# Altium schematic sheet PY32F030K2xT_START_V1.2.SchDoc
size 304 x 241 mm; SheetNumber: 1; SheetTotal: 1
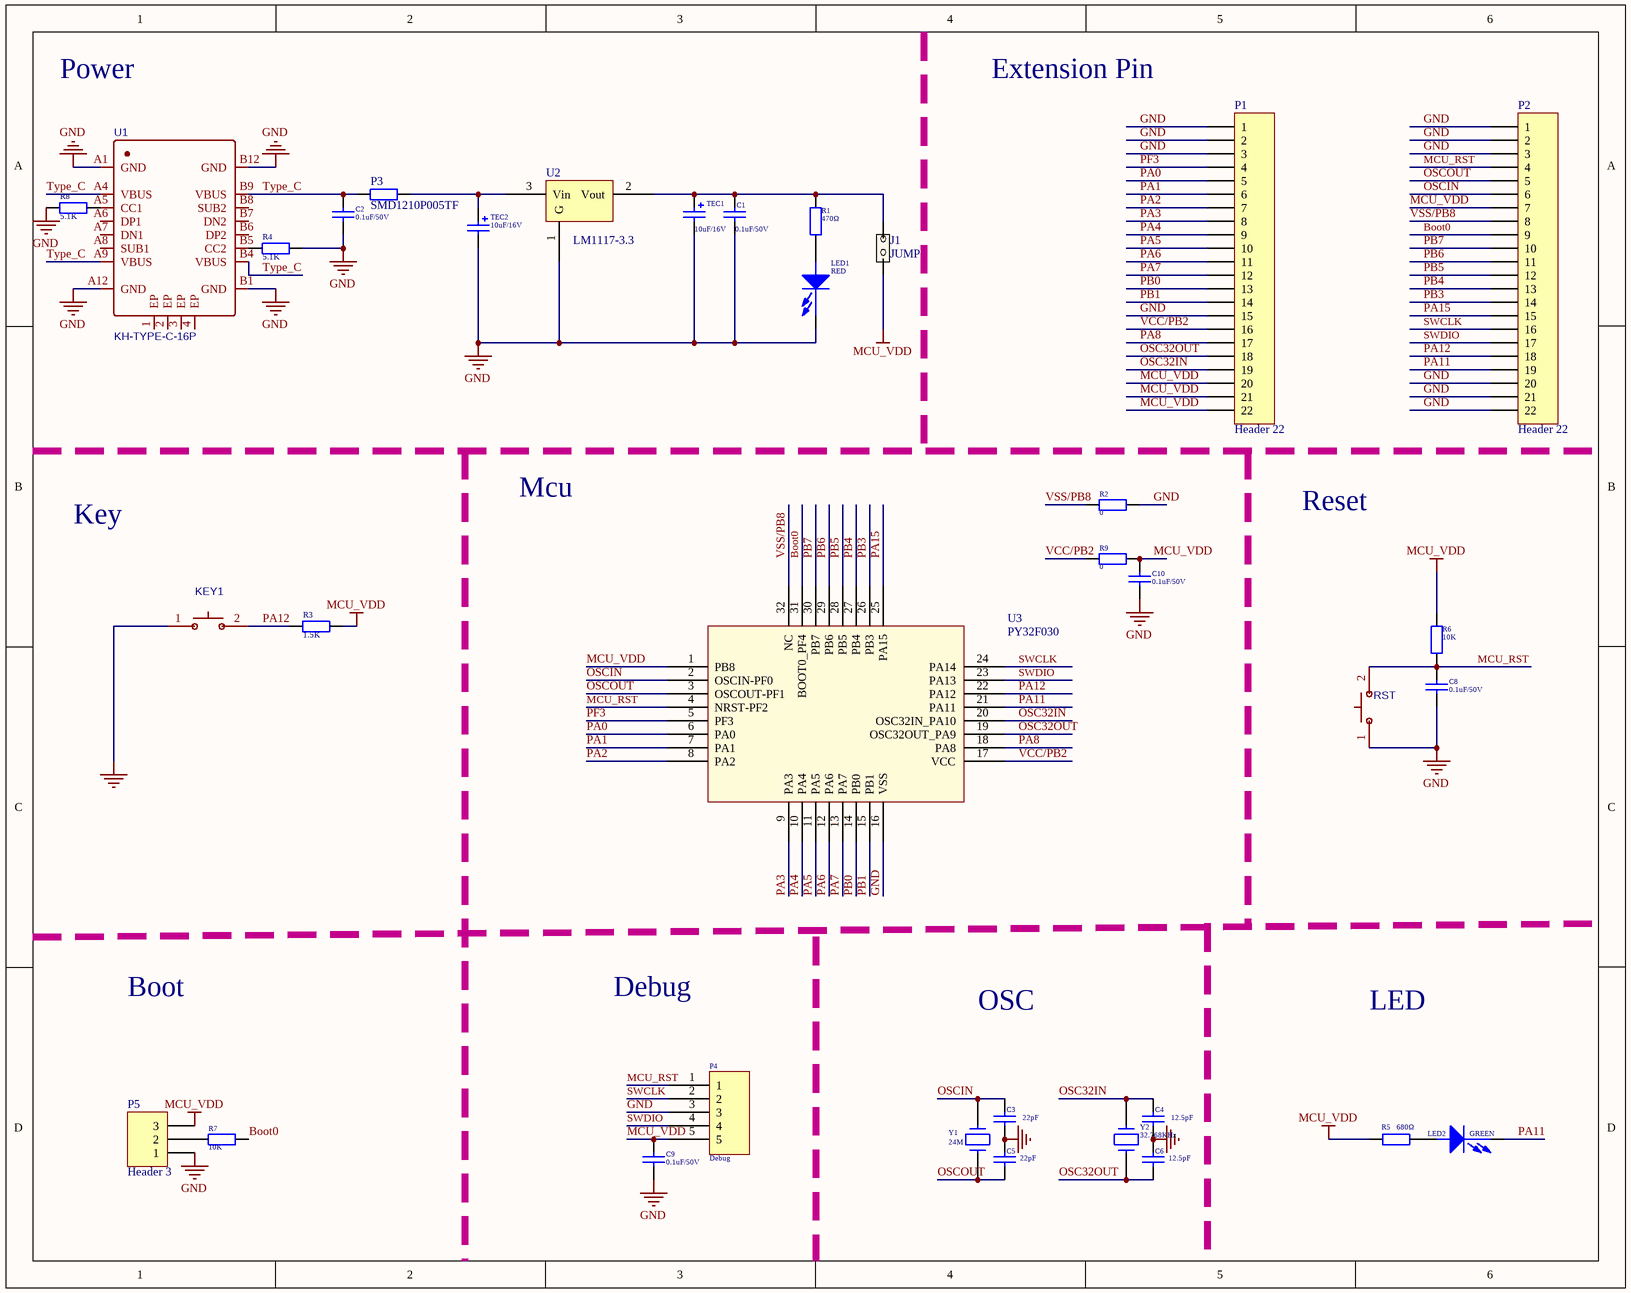
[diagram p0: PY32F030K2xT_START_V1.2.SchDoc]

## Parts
C1  0.1uF/50V  [0603C]
C2  0.1uF/50V  [0603C]
C3  22pF  [0603C]
C4  12.5pF  [0603C]
C5  22pF  [0603C]
C6  12.5pF  [0603C]
C8  0.1uF/50V  [0603C]
C9  0.1uF/50V  [0603C]
C10  0.1uF/50V  [0603C]
J1  JUMP  [HDR1X2]
KEY1  1TS002B-2600-5001  [SW]  (value not drawn)
LED1  RED  [0603_LED]
LED2  GREEN  [0603_LED]
P1  Header 22  [HDR1X22]
P2  Header 22  [HDR1X22]
P3  SMD1210P005TF  [SDM1210P005TF]
P4  Debug  [HDR1X5]
P5  Header 3  [HDR1X3]
R1  470Ω  [0603R]
R2  0  [0603R]
R3  1.5K  [0603R]
R4  5.1K  [0603R]
R5  680Ω  [0603R]
R6  10K  [0603R]
R7  10K  [0603R]
R8  5.1K  [0603R]
R9  0  [0603R]
RST  1TS002B-2600-5001  [SW]  (value not drawn)
TEC1  value 10uF/16V  [0603]  (hidden comment: 10uF)
TEC2  value 10uF/16V  [0603]  (hidden comment: 10uF)
U1  KH-TYPE-C-16P  [USB-C-SMD_KH-TYPE-C-16P]
U2  LM1117-3.3  [LM1117-3.3]
U3  PY32F030  [LQFP32]
Y1  24M  [25MHZ_2]
Y2  32.768KHz  [32768KHZ_2]

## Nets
GND: C1.1 C2.1 C3.1 C4.1 C5.2 C6.2 C8.1 C9.1 C10.1 KEY1.1(A) LED1.2(CATHODE) P1.1 P1.2 P1.3 P1.15 P2.1 P2.2 P2.3 P2.20 P2.21 P2.22 P4.3 P5.1 R2.2 R4.2 R8.1 RST.1(A) TEC1.2 TEC2.2 U1.A1(GND) U1.A12(GND) U1.B1(GND) U1.B12(GND) U2.1(G) U3.16(VSS)
MCU_VDD: C9.2 C10.2 J1.1 P1.20 P1.21 P1.22 P2.7 P4.5 P5.3 R3.2 R5.1 R6.2 R9.2 U3.1(PB8)
Boot0: P2.9 R7.2 U3.31(BOOT0_PF4)
MCU_RST: C8.2 P2.4 P4.1 R6.1 RST.2(B) U3.4(NRST-PF2)
OSC32IN: C4.2 P1.19 U3.20(OSC32IN_PA10) Y2.2
OSC32OUT: C6.1 P1.18 U3.19(OSC32OUT_PA9) Y2.1
OSCIN: C3.2 P2.6 U3.2(OSCIN-PF0) Y1.1
OSCOUT: C5.1 P2.5 U3.3(OSCOUT-PF1) Y1.2
PA0: P1.5 U3.6(PA0)
PA1: P1.6 U3.7(PA1)
PA2: P1.7 U3.8(PA2)
PA3: P1.8 U3.9(PA3)
PA4: P1.9 U3.10(PA4)
PA5: P1.10 U3.11(PA5)
PA6: P1.11 U3.12(PA6)
PA7: P1.12 U3.13(PA7)
PA8: P1.17 U3.18(PA8)
PA11: LED2.2(CATHODE) P2.19 U3.21(PA11)
PA12: KEY1.2(B) P2.18 R3.1 U3.22(PA12)
PA15: P2.15 U3.25(PA15)
PB0: P1.13 U3.14(PB0)
PB1: P1.14 U3.15(PB1)
PB3: P2.14 U3.26(PB3)
PB4: P2.13 U3.27(PB4)
PB5: P2.12 U3.28(PB5)
PB6: P2.11 U3.29(PB6)
PB7: P2.10 U3.30(PB7)
PF3: P1.4 U3.5(PF3)
SWCLK: P2.16 P4.2 U3.24(PA14)
SWDIO: P2.17 P4.4 U3.23(PA13)
Type_C: C2.2 P3.1 U1.A4(VBUS) U1.A9(VBUS) U1.B4(VBUS) U1.B9(VBUS)
VCC/PB2: P1.16 R9.1 U3.17(VCC)
VSS/PB8: P2.8 R2.1 U3.32(NC)
NetC1_2: C1.2 J1.2 R1.1 TEC1.1 U2.2(Vout)
NetLED1_1: LED1.1(ANODE) R1.2
NetLED2_1: LED2.1(ANODE) R5.2
NetP3_2: P3.2 TEC2.1 U2.3(Vin)
NetP5_2: P5.2 R7.1
NetR4_1: R4.1 U1.B5(CC2)
NetR8_2: R8.2 U1.A5(CC1)

Not connected (* = marked no-connect by the designer): U1 1(EP) 2(EP) 3(EP) 4(EP) A6(DP1) A7(DN1) A8(SUB1) B6(DP2) B7(DN2) B8(SUB2)

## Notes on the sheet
- Power
- Extension Pin
- Mcu
- Key
- Reset
- Boot
- Debug
- OSC
- LED

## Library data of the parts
C1 C3-C6 = Cap: Capacitor
C2 C8-C10 = CAP: Capacitor; Value: 2.2uF
KEY1 RST = 1TS002B-2600-5001: BOM_Manufacturer: HYP; Contributor: LCSC
LED1 LED2 = PDI-E803_Dup1
P1 P2 = Header 22: Header, 22-Pin
P4 = CON5
P5 = Header 3: Header, 3-Pin
R1-R3 R5 R9 = Res: Resistor; 器件封装(外观): 0603; Value: 10K
R4 R8 = Res_1: Resistor; 器件封装(外观): 0603; Value: 10K
R6 R7 = Res: Resistor; 器件封装(外观): 0603
TEC1 TEC2 = 贴片钽电容: 器件封装(外观): 3528
U1 = KH-TYPE-C-16P: BOM_Manufacturer: Shenzhen Kinghelm Elec; Contributor: LCSC
Y1 Y2 = CRYSTAL: Value: X503225MSB2GI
